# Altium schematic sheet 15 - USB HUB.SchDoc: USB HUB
size A3; PageSetup: Record=PageOptions¦CenterHorizontal=True¦CenterVertical=True¦PrintScale=0.70¦XCorrection=1.00¦YCorrection=1.00¦PrintKind=0¦BorderSize=5000000¦LeftOffset=0¦BottomOffset=0¦Orientation=2¦PaperLength=4200¦PaperWidth=2970¦Scale=100¦PaperSource=7¦PrintQuality=600¦MediaType=1¦DitherType=10¦PaperKind=A4¦PrintScaleMode=1; Author: Juan Anzola; SheetNumber: 15; SheetTotal: 21
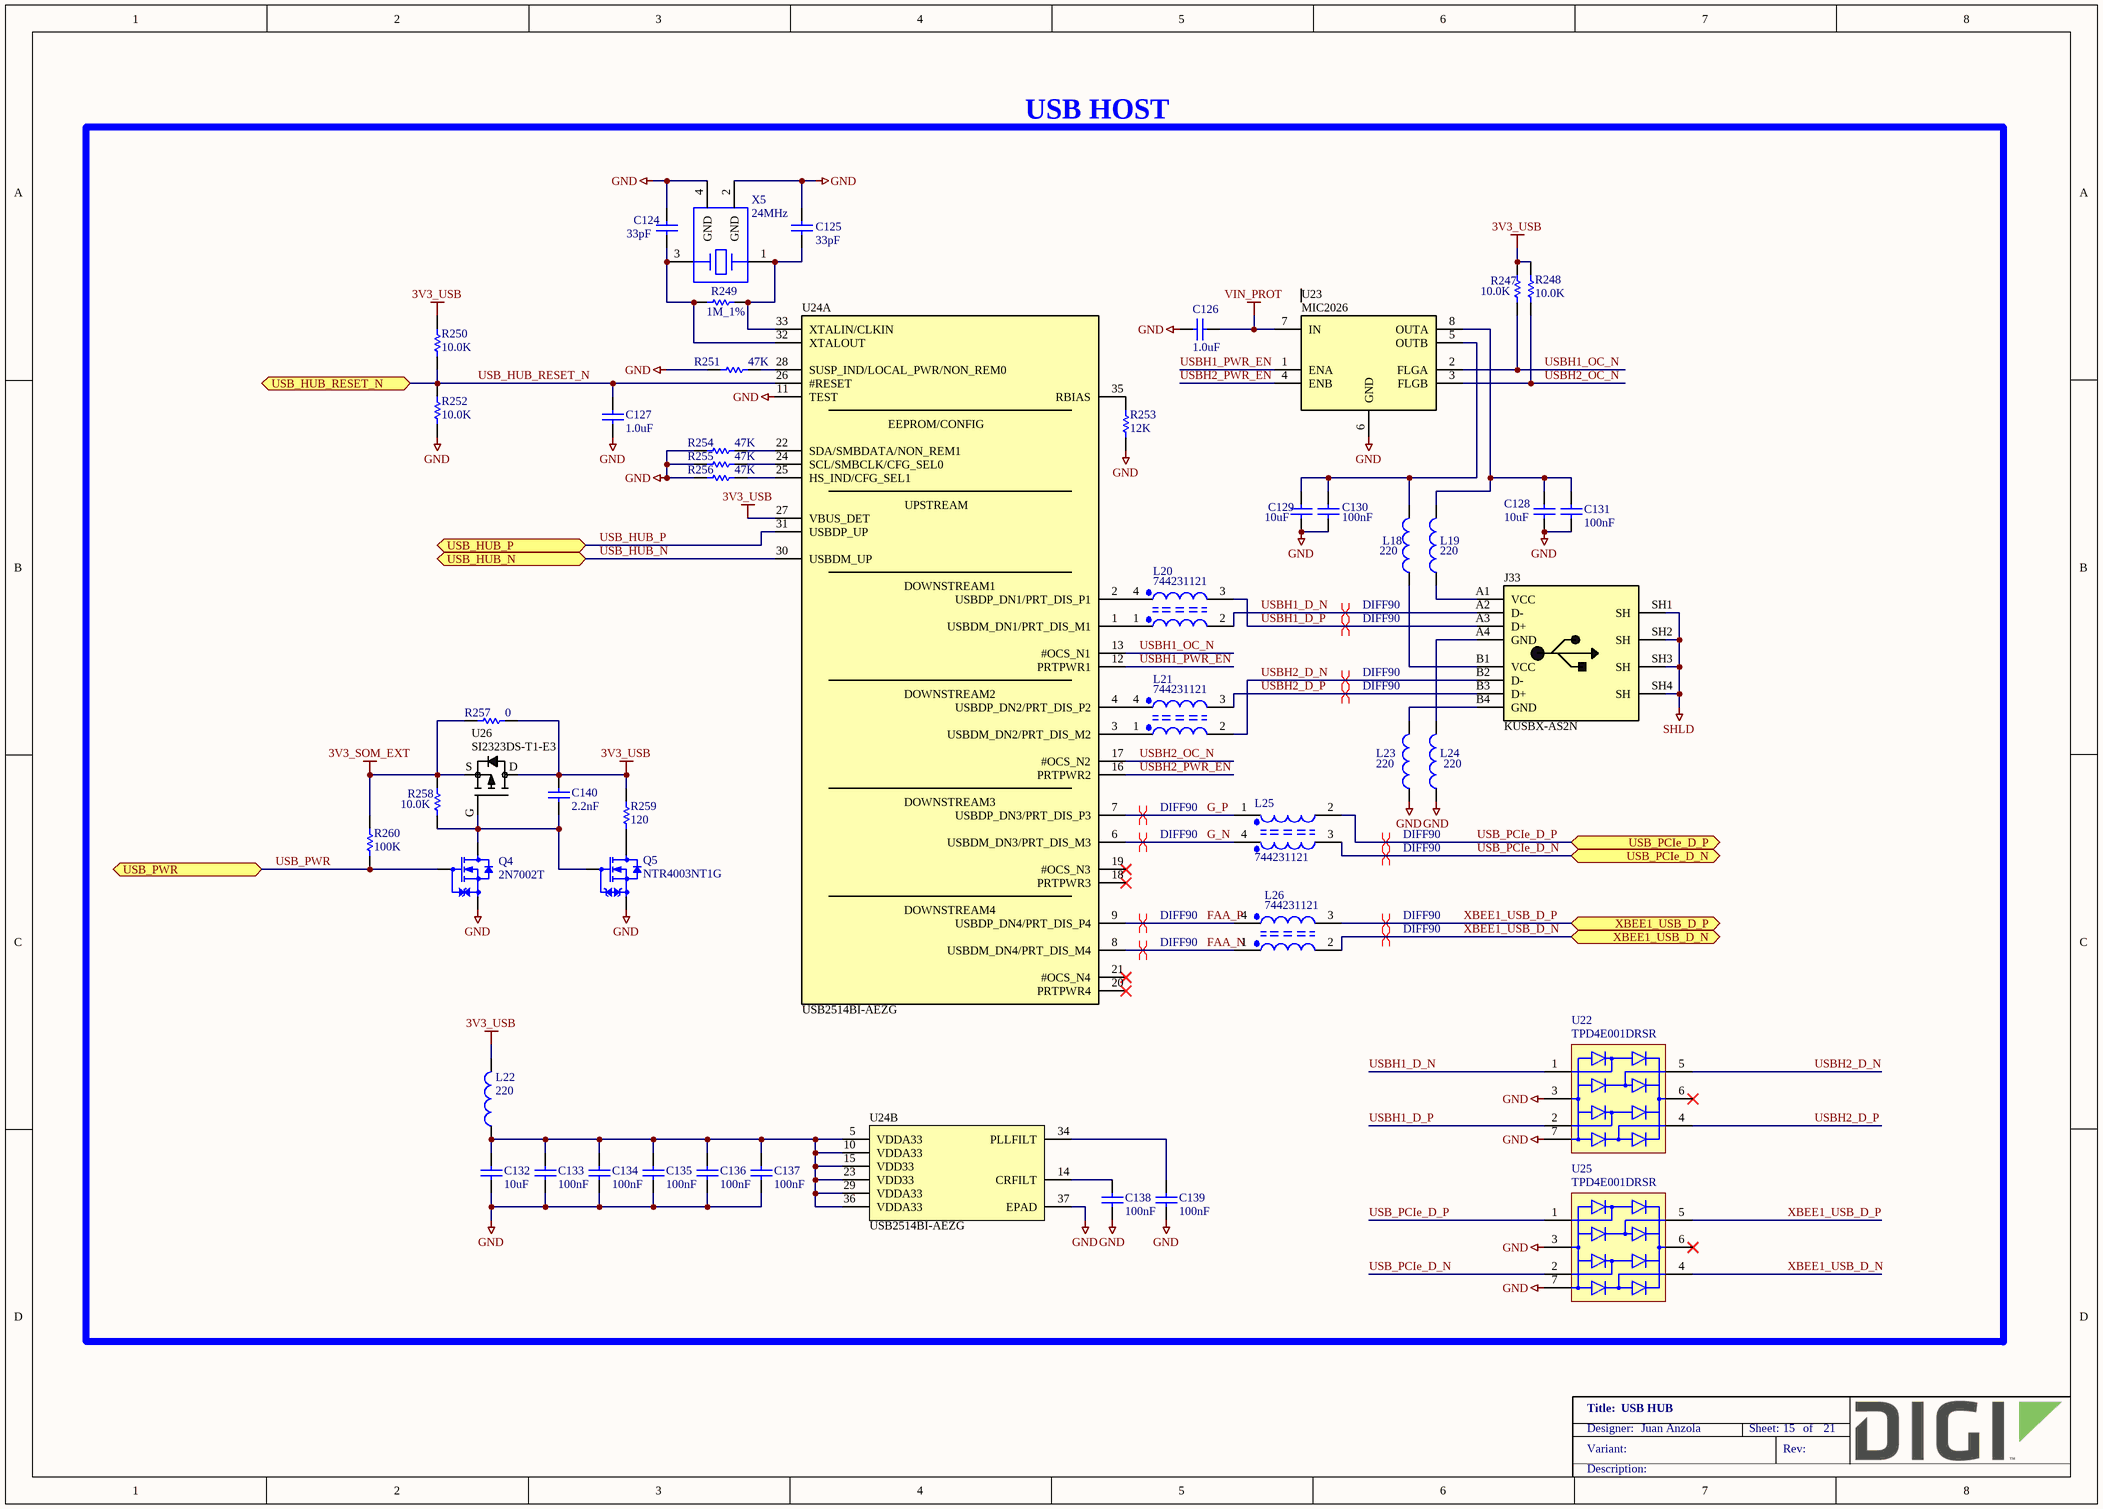
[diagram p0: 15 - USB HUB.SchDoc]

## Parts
C124  33pF  [CAPC1005X55N]
C125  33pF  [CAPC1005X55N]
C126  1.0uF  [CAPC1005X55N]
C127  1.0uF  [CAPC1005X55N]
C128  10uF  [CAPC1005X55N]
C129  10uF  [CAPC1005X55N]
C130  100nF  [CAPC1005X55N]
C131  100nF  [CAPC1005X55N]
C132  10uF  [CAPC1005X55N]
C133  100nF  [CAPC1005X55N]
C134  100nF  [CAPC1005X55N]
C135  100nF  [CAPC1005X55N]
C136  100nF  [CAPC1005X55N]
C137  100nF  [CAPC1005X55N]
C138  100nF  [CAPC1005X55N]
C139  100nF  [CAPC1005X55N]
C140  2.2nF  [CAPC1608X90N]
J33  KUSBX-AS2N  [KYCON_KUSBX-AS2N_Flex]
L18  220  [INDC2013X110N]
L19  220  [INDC2013X110N]
L20  744231121  [FIL_DLW21H]
L21  744231121  [FIL_DLW21H]
L22  220  [INDC2013X110N]
L23  220  [INDC2013X110N]
L24  220  [INDC2013X110N]
L25  744231121  [FIL_DLW21H]
L26  744231121  [FIL_DLW21H]
Q4  2N7002T  [SOTFL50P160X80_GSD-3N]
Q5  NTR4003NT1G  [SOT95P240X110_GSD-3N]
R247  10.0K  [RESC1005X40N]
R248  10.0K  [RESC1005X40N]
R249  1M_1%  [RESC1005X40N]
R250  10.0K  [RESC1005X40N]
R251  47K  [RESC1005X40N]
R252  10.0K  [RESC1005X40N]
R253  12K  [RESC1609X55N]
R254  47K  [RESC1005X40N]
R255  47K  [RESC1005X40N]
R256  47K  [RESC1005X40N]
R257  0  [RESC1609X55N]
R258  10.0K  [RESC1005X40N]
R259  120  [RESC1005X40N]
R260  100K  [RESC1005X40N]
U22  TPD4E001DRSR  [SON95P300X300X80-7N]
U23  MIC2026  [SOIC127P600X175-8N]
U24  USB2514BI-AEZG  [QFN50P600X600X100-37AN]  (parts A,B of 2)
U25  TPD4E001DRSR  [SON95P300X300X80-7N]
U26  SI2323DS-T1-E3  [SOT95P240X110_GSD-3N]
X5  24MHz  [XTAL_C3E-3427]

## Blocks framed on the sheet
USB HOST: C124-C140 J33 L18-L26 Q4 Q5 R247-R260 U22-U26 X5

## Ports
USB_HUB_N (bidir), USB_HUB_P (bidir), USB_HUB_RESET_N (bidir), USB_PCIe_D_N (bidir), USB_PCIe_D_P (bidir), USB_PWR (bidir), XBEE1_USB_D_N (bidir), XBEE1_USB_D_P (bidir)

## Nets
3V3_SOM_EXT: R257.1 R258.1 R260.1 U26.S
3V3_USB: C140.2 L22.2 R247.2 R248.2 R250.2 R257.2 R259.1 U24.27(VBUS_DET) U26.D
GND: C124.2 C125.2 C126.2 C127.1 C128.1 C129.1 C130.1 C131.1 C132.1 C133.1 C134.1 C135.1 C136.1 C137.1 C138.1 C139.1 L23.1 L24.1 Q4.S Q5.S R251.2 R252.1 R253.1 R254.1 R255.1 R256.1 U22.3(GND) U22.7(GND) U23.6(GND) U24.11(TEST) U24.37(EPAD) U25.3(GND) U25.7(GND) X5.2(GND) X5.4(GND)
SHLD: J33.SH1(SH) J33.SH2(SH) J33.SH3(SH) J33.SH4(SH)
VIN_PROT: C126.1 U23.7(IN)
FAA_N: L26.1 U24.8(USBDM_DN4/PRT_DIS_M4)
FAA_P: L26.4 U24.9(USBDP_DN4/PRT_DIS_P4)
G_N: L25.4 U24.6(USBDM_DN3/PRT_DIS_M3)
G_P: L25.1 U24.7(USBDP_DN3/PRT_DIS_P3)
USB_HUB_N: U24.30(USBDM_UP) ; port USB_HUB_N
USB_HUB_P: U24.31(USBDP_UP) ; port USB_HUB_P
USB_HUB_RESET_N: C127.2 R250.1 R252.2 U24.26(#RESET) ; port USB_HUB_RESET_N
USB_PCIe_D_N: L25.3 U25.2(I/O) ; port USB_PCIe_D_N
USB_PCIe_D_P: L25.2 U25.1(I/O) ; port USB_PCIe_D_P
USB_PWR: Q4.G R260.2 ; port USB_PWR
USBH1_D_N: J33.A2(D-) L20.2 U22.1(I/O)
USBH1_D_P: J33.A3(D+) L20.3 U22.2(I/O)
USBH1_OC_N: R247.1 U23.2(FLGA) U24.13(#OCS_N1)
USBH1_PWR_EN: U23.1(ENA) U24.12(PRTPWR1)
USBH2_D_N: J33.B2(D-) L21.2 U22.5(I/O)
USBH2_D_P: J33.B3(D+) L21.3 U22.4(I/O)
USBH2_OC_N: R248.1 U23.3(FLGB) U24.17(#OCS_N2)
USBH2_PWR_EN: U23.4(ENB) U24.16(PRTPWR2)
XBEE1_USB_D_N: L26.2 U25.4(I/O) ; port XBEE1_USB_D_N
XBEE1_USB_D_P: L26.3 U25.5(I/O) ; port XBEE1_USB_D_P
NetC124_1: C124.1 R249.1 U24.32(XTALOUT) X5.3
NetC125_1: C125.1 R249.2 U24.33(XTALIN/CLKIN) X5.1
NetC128_2: C128.2 C131.2 L19.2 U23.8(OUTA)
NetC129_2: C129.2 C130.2 L18.2 U23.5(OUTB)
NetC132_2: C132.2 C133.2 C134.2 C135.2 C136.2 C137.2 L22.1 U24.5(VDDA33) U24.10(VDDA33) U24.15(VDD33) U24.23(VDD33) U24.29(VDDA33) U24.36(VDDA33)
NetC138_2: C138.2 U24.14(CRFILT)
NetC139_2: C139.2 U24.34(PLLFILT)
NetC140_1: C140.1 Q4.D Q5.G R258.2 U26.G
NetJ33_A1: J33.A1(VCC) L19.1
NetJ33_A4: J33.A4(GND) L24.2
NetJ33_B1: J33.B1(VCC) L18.1
NetJ33_B4: J33.B4(GND) L23.2
NetL20_1: L20.1 U24.1(USBDM_DN1/PRT_DIS_M1)
NetL20_4: L20.4 U24.2(USBDP_DN1/PRT_DIS_P1)
NetL21_1: L21.1 U24.3(USBDM_DN2/PRT_DIS_M2)
NetL21_4: L21.4 U24.4(USBDP_DN2/PRT_DIS_P2)
NetQ5_D: Q5.D R259.2
NetR251_1: R251.1 U24.28(SUSP_IND/LOCAL_PWR/NON_REM0)
NetR253_2: R253.2 U24.35(RBIAS)
NetR254_2: R254.2 U24.22(SDA/SMBDATA/NON_REM1)
NetR255_2: R255.2 U24.24(SCL/SMBCLK/CFG_SEL0)
NetR256_2: R256.2 U24.25(HS_IND/CFG_SEL1)

Not connected (* = marked no-connect by the designer): U22 6(VCC)*; U24 18(PRTPWR3)* 19(#OCS_N3)* 20(PRTPWR4)* 21(#OCS_N4)*; U25 6(VCC)*

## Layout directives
differential pair; net class DIFF90: FAA_N, FAA_P, G_N, G_P, USB_PCIe_D_N, USB_PCIe_D_P, USBH1_D_N, USBH1_D_P, USBH2_D_N, USBH2_D_P, XBEE1_USB_D_N, XBEE1_USB_D_P

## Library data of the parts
C124 C125 = 1002646: CAP CER 33PF 50V C0G/NP0 0402; Part_Type: Capacitor; Manufacturer: Murata; Manufacturer_Part_Number: GCM1555C1H330JA16D; Digi_PN: 14050400; Component_Life_Cycle_State: Reviewed; Area: 2,12; Voltage: 50; Tolerance: 5%
C126 C127 = 1001167: CAP CER 1UF 10V 10% X5R 0402; Part_Type: Capacitor; Manufacturer: Murata; Manufacturer_Part_Number: GRM155R61A105KE15D; Digi_PN: 14050399; Component_Life_Cycle_State: Reviewed; Area: 0.95; Project: CCWMX6_SBC board
C128 C129 C132 = 1001168: CAP CER 10UF 10V 20% X5R 0402; Part_Type: Capacitor; Manufacturer: Samsung; Manufacturer_Part_Number: CL05A106MP5NUNC; Digi_PN: 14050689; Component_Life_Cycle_State: Reviewed; Area: 0.95; Project: CCWMX6_SBC board
C130 C131 C133-C139 = 1000006: CAP 100nF 16V 10% X7R 0402; Part_Type: Capacitor; Manufacturer: Murata; Manufacturer_Part_Number: GRM155R71C104KA88D; Component_Life_Cycle_State: CAD Reviewed; Area: 0.95; Project: KITT; Tolerance: 10; Digi_PN: 14050552
C140 = 1002727: CAP CER 2200PF 50V X7R 5% 0603; Part_Type: Capacitor; Manufacturer: Kemet; Manufacturer_Part_Number: C0603C222J5RACTU; Digi_PN: 14050443; Component_Life_Cycle_State: Pending; Area: 2,27
J33 = 1001121: USB Stacked Dual A type; Part_Type: Connector; Manufacturer: KYCON; Digi_PN: 18000276; Component_Life_Cycle_State: Reviewed; Area: 164; Project: CCWMX6_SBC board
L18 L19 L22-L24 = 1001174: FERRITE BEAD 220 OHM 2.0A 0805; Manufacturer: Wurth Electronics Inc; Manufacturer_Part_Number: 742792022; Digi_PN: 21000146; Component_Life_Cycle_State: Reviewed; Area: 4.24; Project: CCWMX6_SBC board
L20 L21 L25 L26 = 1001173: CHOKE COM MODE 120 OHM .37A; Part_Type: Inductor; Manufacturer: Wurth Electronics Inc; Digi_PN: 21000143; Component_Life_Cycle_State: Reviewed; Area: 2.4; Project: CCWMX6_SBC board
Q4 = 1000715: MOSFET N-CH 60V 115MA SOT-523F; Part_Type: Transistor; Manufacturer: Fairchild Semiconductor; Digi_PN: 17050797; Component_Life_Cycle_State: CAD Reviewed; Area: 3.06; Project: SmartMeter2; Note: 17050841 = Digi No. for GE WDNU
Q5 = 1000306: MOSFET N-CH 30V 500MA SOT-23; Part_Type: Transistor; Manufacturer: On Semiconductor; Digi_PN: 17050809; Component_Life_Cycle_State: Proven; Area: 10,92; Project: Adjustable Foundation
R247 R248 R250 R252 R258 = 1000537: RES 10.0K OHM 1/10W 1% 0402 SMD; Part_Type: Resistor; Manufacturer: Panasonic - ECG; Manufacturer_Part_Number: ERJ-2RKF1002X; Component_Life_Cycle_State: CAD Reviewed; Area: 0.95; Project: KITT; Power_WV_SRF: 100; Digi_PN: 13051084
R249 = 1000971: RES 1.00M OHM 1/16W 1% 0402 SMD; Part_Type: Resistor; Manufacturer: Yageo; Manufacturer_Part_Number: RC0402FR-071ML; Digi_PN: 13050561; Component_Life_Cycle_State: Reviewed; Area: 0.95; Project: ConnectCore i.MX6 module; Power_WV_SRF: 63; Tolerance: 1; Note: 13051098 = Digi No. for GE WDNU
R251 R254-R256 = 1001155: RES 47.0K OHM 1/16W 1% 0402 SMD; Part_Type: Resistor; Manufacturer: Vishay Dale; Manufacturer_Part_Number: CRCW040247K0FKED; Digi_PN: 13050646; Component_Life_Cycle_State: Reviewed; Area: 0.95; Project: CCWMX6_SBC board
R253 = 1001200: RES 12.0K OHM 1/10W 1% 0603 SMD; Part_Type: Resistor; Manufacturer: Yageo; Manufacturer_Part_Number: RC0603FR-0712KL; Digi_PN: 13050531; Component_Life_Cycle_State: Reviewed; Area: 2.5; Project: LuCoV2; Power_WV_SRF: 100; Tolerance: 1
R257 = 1000208: RES 0.0 OHM 1/10W 0603; Part_Type: Resistor; Manufacturer: Panasonic - ECG; Manufacturer_Part_Number: ERJ-3GEY0R00V; Note: 13051103 = Digi No. for GE WDNU; Digi_PN: 13050568; Component_Life_Cycle_State: Reviewed; Area: 2.5; Project: Adjustable Foundation; Voltage: 75V
R259 = 1001158: RES 120 OHM 1/16W 1% 0402 SMD; Part_Type: Resistor; Manufacturer: Yageo; Manufacturer_Part_Number: RC0402FR-07120RL; Digi_PN: 13050832; Component_Life_Cycle_State: Reviewed; Area: 0.95; Project: CCWMX6_SBC board; Note: 13051102 = Digi No. for GE WDNU
R260 = 1000480: RES 100K OHM 1/10W 1% 0402 SMD; Part_Type: Resistor; Manufacturer: Panasonic - ECG; Manufacturer_Part_Number: ERJ-2RKF1003X; Digi_PN: 13051063; Component_Life_Cycle_State: CAD Reviewed; Area: 0.95; Project: KITT; Power_WV_SRF: 100
U22 U25 = 1001265: TVS DIODE 5.5VWM 6SON; Part_Type: IC; Manufacturer: Texas Instruments; Digi_PN: 17050690; Component_Life_Cycle_State: Reviewed; Area: 10; Project: CCWMX6_SBC board; Note: 17050839 = Digi No. for GE WDNU
U23 = 1001143: IC SW DISTRIBUTION 2CHAN 8SOIC; Manufacturer: Micrel; Manufacturer_Part_Number: MIC2026-1YM; Digi_PN: 16051879; Component_Life_Cycle_State: Reviewed; Area: 29.58; Project: CCWMX6_SBC board
U24 = 1001114: 4-PORT USB 2.0 HUB CTRLR 36VQFN; Part_Type: IC; Manufacturer: SMSC; Digi_PN: 16051280; Component_Life_Cycle_State: Reviewed; Area: 36; Project: CCWMX6_SBC board
U26 = 1001163: MOSFET P-CH 20V 3.7A SOT23-3; Part_Type: IC; Manufacturer: Vishay Siliconix; Digi_PN: 17050358; Component_Life_Cycle_State: Reviewed; Area: 10.92; Project: CCWMX6_SBC board
X5 = 1001134: CRYSTAL 24MHZ 18PF SMD; Part_Type: Crystals-Oscillators; Manufacturer: Aker; Manufacturer_Part_Number: C3E-24.000-18-3030-X-R; Digi_PN: 20000223; Component_Life_Cycle_State: Reviewed; Area: 9.18; Project: CCWMX6_SBC board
